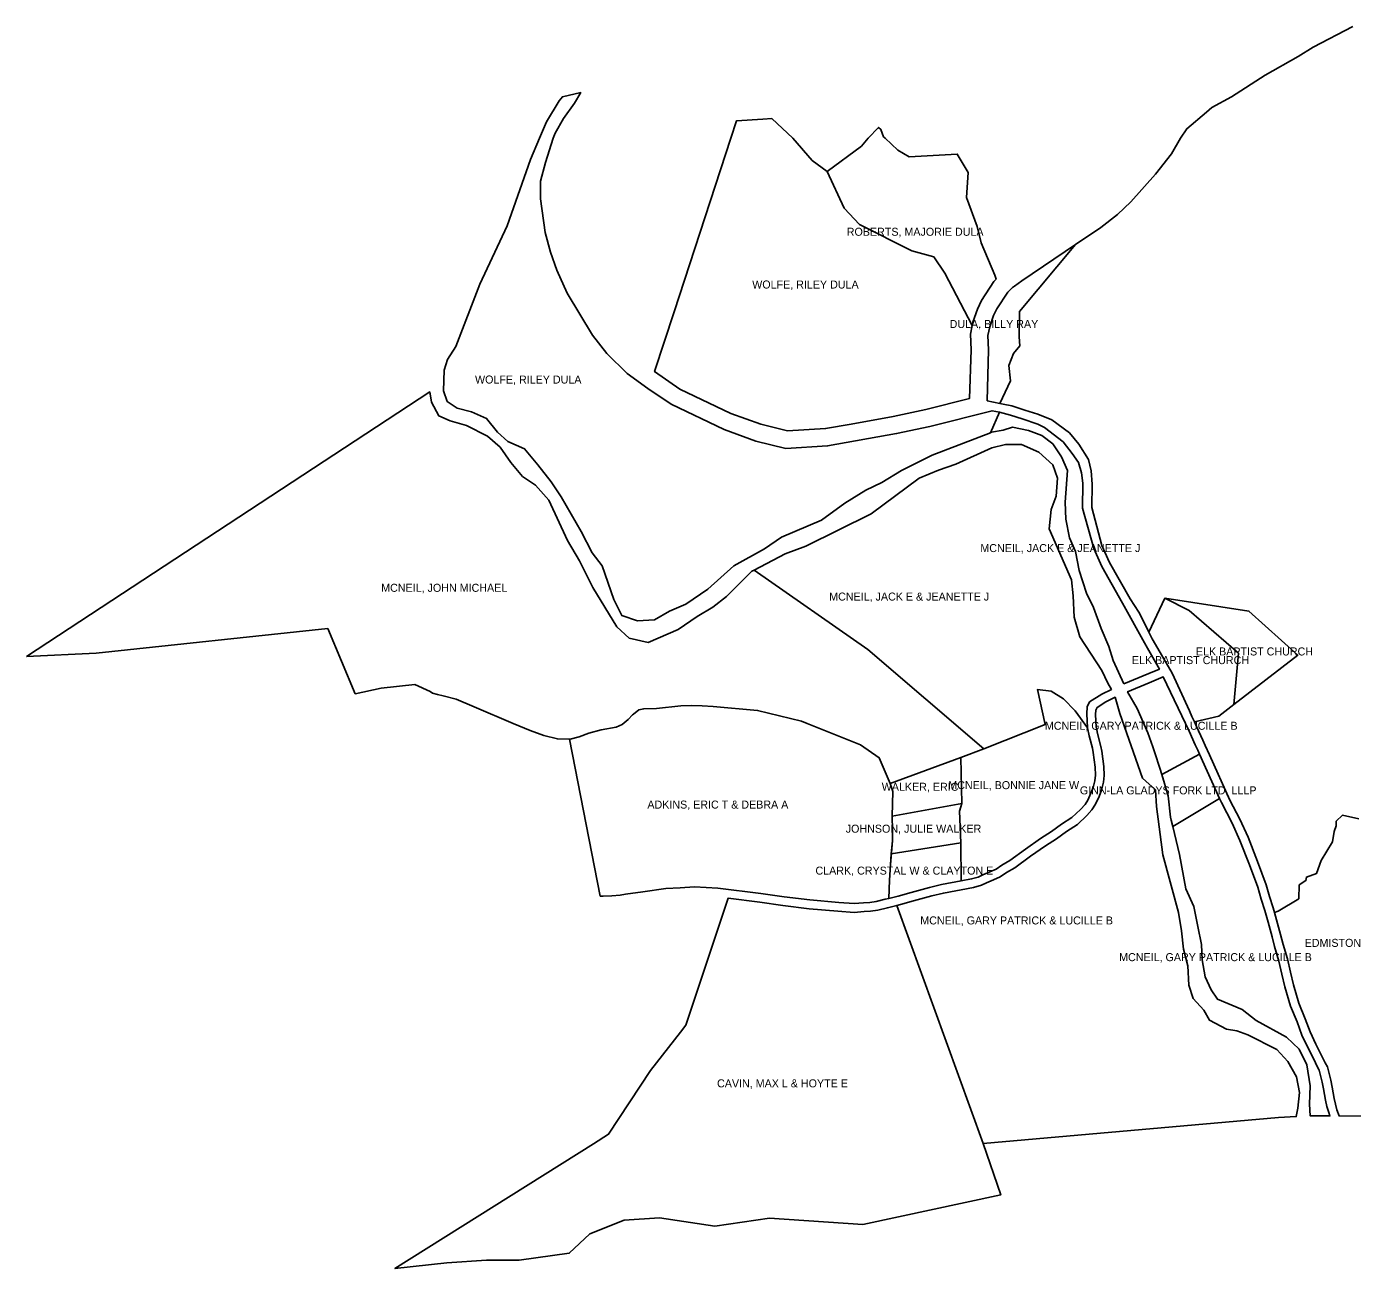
# Model space of a CAD drawing. Extents: x 1282784 to 1290548, y 856119 to 860542.
# Drawn here: x 1282784 to 1287337, y 856119 to 860383 of the extents above; entities that cross this region are included whole.
import ezdxf

# ---------------------------------------------------------------- set-up
doc = ezdxf.new("R2010")
doc.units = 0
doc.layers.add('WILKES_2010PARCELS', color=7, linetype='Continuous')

msp = doc.modelspace()

# ---------------------------------------------------------------- linework, layer by layer
at = {"layer": 'WILKES_2010PARCELS'}
for points in [[(1286746.375, 860000), (1286767.625, 860031.8125), (1286835.375, 860089.0625), (1286853.625, 860104.4375), (1286920.75, 860142.1875), (1287037.125, 860216.1875), (1287149.875, 860279.8125), (1287201.75, 860312.6875), (1287338, 860383)], [(1284545.25, 860000), (1284569.375, 860055.5625), (1284612.25, 860127.5625), (1284623.75, 860141.75), (1284686.375, 860156.5), (1284665.625, 860119.6875), (1284627.75, 860066.6875), (1284598.5, 860016.6875), (1284591.375, 860000)], [(1285201.375, 860000), (1285220.875, 860058.6875), (1285311.25, 860065), (1285342.875, 860067.1875), (1285415.375, 860000)], [(1285673.875, 860000), (1285709.25, 860036.75), (1285717.25, 860030), (1285726, 860004.8125), (1285731.75, 860000)], [(1284591.375, 860000), (1284565, 859916.1875), (1284548.125, 859851.875), (1284548.25, 859791.5), (1284564, 859675.5), (1284582.5, 859608.125), (1284604.125, 859546.3125), (1284639.375, 859467.8125), (1284726.875, 859323.8125), (1284776.375, 859261), (1284845.75, 859191.5625), (1284917, 859140.75), (1284996.875, 859086), (1285178.75, 858999.125), (1285287.625, 858960.0625), (1285391.25, 858934.1875), (1285534.375, 858943), (1285771.125, 858985.4375), (1285884.875, 859010), (1286098.75, 859063.75), (1286125, 859058.8125), (1286093.75, 858988.6875), (1285893, 858911.1875), (1285788.5, 858858.375), (1285720.5, 858818), (1285665.25, 858790.75), (1285592.875, 858747.125), (1285513.625, 858687.9375), (1285376, 858630.3125), (1285317.5, 858589.875), (1285211.875, 858531.0625), (1285123.5, 858451.875), (1285047.875, 858400.25), (1284991.875, 858375.8125), (1284939.75, 858346.1875), (1284881.75, 858342.1875), (1284827.75, 858360.625), (1284799.75, 858415.8125), (1284759.75, 858531.0625), (1284725.75, 858576.6875), (1284687.75, 858649.9375), (1284619.25, 858768.75), (1284585.25, 858820.375), (1284539.625, 858878.8125), (1284493.625, 858933.25), (1284436, 858958.8125), (1284400.875, 858990.8125), (1284363.25, 859037.25), (1284311.125, 859060.0625), (1284262, 859072.875), (1284228, 859096.0625), (1284215.125, 859132.5), (1284218, 859202.9375), (1284229.125, 859239.3125), (1284258, 859284.125), (1284340.375, 859499), (1284433.625, 859698.3125), (1284513.625, 859926.375), (1284545.25, 860000)], [(1285415.375, 860000), (1285480.75, 859923.5625), (1285533.125, 859885.8125), (1285591.25, 859759.125), (1285644, 859703.125), (1285823.375, 859612.6875), (1285898.5, 859592.25), (1285937, 859536.25), (1286030.5, 859356.8125), (1286024.5, 859326.5), (1286026.625, 859273.125), (1286022, 859106.125), (1285871.375, 859068.5), (1285759.375, 859044.3125), (1285615.25, 859018), (1285527.375, 859002.625), (1285396.75, 858994.6875), (1285305.125, 859017.5625), (1285201.75, 859054.625), (1285026.875, 859138.125), (1284939.875, 859198.1875), (1285006.875, 859403.0625), (1285201.375, 860000)], [(1285731.75, 860000), (1285775.125, 859958), (1285813.875, 859936), (1285979.375, 859944.8125), (1286017, 859882.375), (1286011.375, 859796.3125), (1286047.75, 859696.3125), (1286061, 859640.25), (1286108.25, 859529.8125), (1286112.875, 859516.1875), (1286104.5, 859508.1875), (1286062.25, 859442.625), (1286048.875, 859413.125), (1286032.75, 859368.5625), (1286030.5, 859356.8125), (1285937, 859536.25), (1285898.5, 859592.25), (1285823.375, 859612.6875), (1285644, 859703.125), (1285591.25, 859759.125), (1285533.125, 859885.8125), (1285650.5, 859972), (1285673.875, 860000)], [(1287357.875, 857663.375), (1287301.875, 857675.375), (1287281, 857655.375), (1287280.625, 857638.5625), (1287273.375, 857619.75), (1287268.25, 857583.6875), (1287228.625, 857520.4375), (1287213, 857475.5625), (1287178.5, 857463.1875), (1287176.5, 857450.75), (1287153.75, 857436.3125), (1287152.875, 857388.6875), (1287081.25, 857345.8125), (1287068.75, 857341.75), (1287064.375, 857357), (1287051.625, 857396.4375), (1287039.75, 857436.6875), (1287010.5, 857516), (1286978, 857599.75), (1286950, 857661.3125), (1286915.625, 857727.5625), (1286845.125, 857882.6875), (1286830.375, 857915.25), (1286822.125, 857933.1875), (1286800.75, 857979.75), (1286793.5, 857995.625), (1286877.875, 858014.9375), (1286929.625, 858055.0625), (1287149.25, 858225.125), (1286980.75, 858376.0625), (1286692.375, 858420.125), (1286637.375, 858303.625), (1286631.125, 858315.8125), (1286602.5, 858372.1875), (1286573, 858418.5625), (1286502, 858543.375), (1286476, 858601.875), (1286441.375, 858731.9375), (1286442.25, 858811.6875), (1286438.75, 858857.375), (1286430.625, 858896.8125), (1286396.625, 858949.6875), (1286364.375, 858988.25), (1286304.25, 859032.1875), (1286255.875, 859051.875), (1286211.125, 859066.1875), (1286167.375, 859080.875), (1286137.5, 859086.875), (1286125.375, 859089.3125), (1286162.75, 859166.875), (1286156.25, 859219.75), (1286172.25, 859261), (1286193.875, 859287), (1286191.5, 859317.4375), (1286193.5, 859404.75), (1286385.375, 859634.25), (1286472.75, 859693.1875), (1286529.375, 859737.125), (1286575.5, 859780.75), (1286659.75, 859876.6875), (1286715.125, 859946.3125), (1286746.375, 860000)], [(1287423.75, 856642.4375), (1287290.5, 856642.8125), (1287290.25, 856643.75), (1287283.25, 856664.25), (1287277.75, 856683.0625), (1287273.375, 856703), (1287266.5, 856742.0625), (1287261.75, 856765.6875), (1287256, 856788.875), (1287250.875, 856811.8125), (1287243.125, 856824.8125), (1287229.375, 856853.1875), (1287211.125, 856888.875), (1287190.75, 856931.8125), (1287174.625, 856976.5625), (1287151.75, 857030.25), (1287133.625, 857093.625), (1287123.375, 857137.0625), (1287112.875, 857182.4375), (1287098, 857232.0625), (1287089.875, 857265.3125), (1287076, 857316.375), (1287068.75, 857341.75), (1287081.25, 857345.8125), (1287152.875, 857388.6875), (1287153.75, 857436.3125), (1287176.5, 857450.75), (1287178.5, 857463.1875), (1287213, 857475.5625), (1287228.625, 857520.4375), (1287268.25, 857583.6875), (1287273.375, 857619.75), (1287280.625, 857638.5625), (1287281, 857655.375), (1287301.875, 857675.375), (1287357.875, 857663.375)]]:
    msp.add_lwpolyline(points, dxfattribs=at)
for points in [[(1286081.75, 859098), (1286086.625, 859273.5), (1286084.75, 859321.875), (1286090.75, 859352.5625), (1286104.375, 859390.5), (1286115, 859413.75), (1286152.75, 859471.3125), (1286168.75, 859486.75), (1286175.5, 859491.625), (1286201, 859510), (1286385.375, 859634.25), (1286193.5, 859404.75), (1286191.5, 859317.4375), (1286193.875, 859287), (1286172.25, 859261), (1286156.25, 859219.75), (1286162.75, 859166.875), (1286125.375, 859089.3125)], [(1282783.5, 858220.6875), (1284168.25, 859128.3125), (1284173.875, 859092.875), (1284199.125, 859046.0625), (1284238, 859029.625), (1284294.75, 859013.625), (1284366, 858976.4375), (1284409.625, 858938.4375), (1284446, 858886.8125), (1284486.875, 858838), (1284530.875, 858808.75), (1284576.5, 858757.1875), (1284640.875, 858617.9375), (1284681.75, 858549.0625), (1284727.75, 858456.625), (1284811, 858321.8125), (1284853.375, 858283), (1284918.625, 858268.1875), (1285021, 858312.625), (1285085.875, 858357.8125), (1285140.25, 858389.8125), (1285187.5, 858426.625), (1285274.375, 858512.6875), (1285281.75, 858516.5625), (1285672.125, 858244.4375), (1286070.625, 857903.5), (1285992, 857873.875), (1285749.25, 857783.875), (1285711.375, 857872.5625), (1285647.625, 857916.4375), (1285464.25, 857990), (1285444.75, 857997.8125), (1285293.625, 858034.875), (1285141, 858049.0625), (1285103.75, 858050.9375), (1285066.125, 858051.8125), (1285029.875, 858050.6875), (1284947.125, 858041.5), (1284903.125, 858040.625), (1284886, 858036.6875), (1284867.25, 858022.6875), (1284864.625, 858019.875), (1284849.125, 858003.5), (1284829.25, 857986.375), (1284808.5, 857977.125), (1284757, 857968.375), (1284714.25, 857956.8125), (1284681.125, 857944.25), (1284650.25, 857936), (1284648.375, 857936.0625), (1284606.75, 857937.5), (1284559.5, 857949.375), (1284512.5, 857966.375), (1284454.375, 857990.0625), (1284320.5, 858047), (1284258.25, 858073.25), (1284213.625, 858085.4375), (1284194.25, 858089.3125), (1284177.875, 858093.8125), (1284170, 858099.8125), (1284116.875, 858124), (1284001.75, 858111.3125), (1283912.25, 858092.25), (1283818.125, 858316), (1283022.625, 858232.1875)], [(1286551.125, 858126.1875), (1286515.125, 858206.1875), (1286500.375, 858254.1875), (1286473.125, 858316.625), (1286447.125, 858388.25), (1286423.125, 858437.4375), (1286397.875, 858515.5), (1286385.125, 858580.3125), (1286365.125, 858627.125), (1286352.375, 858691.9375), (1286349.875, 858750.375), (1286358.375, 858858.8125), (1286337.125, 858905.1875), (1286307.5, 858950), (1286269.875, 858978.8125), (1286223.5, 858996.4375), (1286169.5, 859007.25), (1286137, 858996.8125), (1286097.375, 858990.0625), (1286093.75, 858988.6875), (1286125, 859058.8125), (1286161.75, 859049.1875), (1286202.125, 859036.625), (1286255.875, 859017.8125), (1286279.125, 859006.1875), (1286342.75, 858957.75), (1286374.125, 858917.4375), (1286395.625, 858886.0625), (1286405.5, 858851.125), (1286410.875, 858815.25), (1286409.125, 858729.25), (1286448, 858590.75), (1286475.5, 858529.125), (1286547, 858403.5625), (1286622.375, 858266.625), (1286632.5, 858248.875), (1286673.625, 858177.1875), (1286637.25, 858162)], [(1286070.625, 857903.5), (1285672.125, 858244.4375), (1285281.75, 858516.5625), (1285388.375, 858572.6875), (1285460, 858599.125), (1285683.25, 858709.9375), (1285848.125, 858832.375), (1285914.5, 858860), (1285974.625, 858880.8125), (1286097.875, 858936.8125), (1286145.5, 858948.4375), (1286199.875, 858947.625), (1286259.125, 858921.625), (1286307.875, 858878.375), (1286323.125, 858832), (1286319.125, 858770.75), (1286301.875, 858724.75), (1286295.5, 858658.3125), (1286371.875, 858483.0625), (1286377.5, 858429.0625), (1286380.375, 858355.4375), (1286400.75, 858287.8125), (1286476.375, 858172.125), (1286496.375, 858128.9375), (1286509, 858107.375), (1286475.375, 858091.25), (1286433.5, 858064.1875), (1286425.875, 858047.125), (1286424, 858023.8125), (1286427, 857975.5625), (1286383.75, 858034.1875), (1286343.75, 858075.375), (1286301.75, 858101.375), (1286255.375, 858107.375), (1286281.5, 857986.75)], [(1286776.375, 858033.25), (1286716.875, 858163.5), (1286651.875, 858275.75), (1286648.875, 858281), (1286637.375, 858303.625), (1286692.375, 858420.125), (1286776.125, 858378.5), (1286945.5, 858231.5625), (1286929.625, 858055.0625), (1286877.875, 858014.9375), (1286793.5, 857995.625), (1286784.875, 858014.5625)], [(1286929.625, 858055.0625), (1286945.5, 858231.5625), (1286776.125, 858378.5), (1286692.375, 858420.125), (1286980.75, 858376.0625), (1287149.25, 858225.125)], [(1285995.5, 857715.4375), (1285992, 857873.875), (1286070.625, 857903.5), (1286281.5, 857986.75), (1286255.375, 858107.375), (1286301.75, 858101.375), (1286343.75, 858075.375), (1286383.75, 858034.1875), (1286427, 857975.5625), (1286432.25, 857948), (1286443.375, 857905.3125), (1286445.875, 857890.875), (1286452.75, 857840.125), (1286454.125, 857812.8125), (1286451.625, 857793.8125), (1286446.375, 857770.5), (1286438.5, 857750.9375), (1286428.125, 857727.25), (1286418.25, 857712.5625), (1286402.5, 857695.5625), (1286373.125, 857667.5625), (1286337.75, 857644.375), (1286303, 857619.3125), (1286265.25, 857595.625), (1286213.25, 857559), (1286160.5, 857520.1875), (1286133, 857503.625), (1286112.75, 857490.1875), (1286091.75, 857481), (1286067.625, 857471.125), (1286051.75, 857463.125), (1286028.625, 857456.6875), (1285992.75, 857449.875), (1285991.75, 857580.4375), (1285987.5, 857689.25)], [(1286650.625, 857910.125), (1286634.375, 857958.0625), (1286596.75, 858042.125), (1286564, 858099), (1286638.875, 858130.1875), (1286686.625, 858150.0625), (1286775.25, 857963.625), (1286796.75, 857916.625), (1286805.125, 857898.1875), (1286811.375, 857884.5), (1286681.625, 857814.875), (1286674.5, 857837.25), (1286657.75, 857889.3125)], [(1286068.625, 856548.25), (1285771.625, 857365.6875), (1285784.5, 857368.9375), (1285829.375, 857381.5625), (1285891.875, 857398.1875), (1285931.75, 857407.8125), (1286035.375, 857427.4375), (1286062.5, 857435), (1286080.125, 857443.75), (1286103.5, 857453.375), (1286127.25, 857463.8125), (1286149, 857478.25), (1286177.25, 857495.1875), (1286230.75, 857534.625), (1286282, 857570.625), (1286319.75, 857594.4375), (1286354.75, 857619.625), (1286391.875, 857643.9375), (1286424, 857674.5625), (1286441.75, 857693.9375), (1286454.375, 857712.75), (1286466.25, 857739.3125), (1286475.125, 857761.625), (1286481.125, 857788.5625), (1286484.125, 857811.5625), (1286482.75, 857842.875), (1286475.625, 857895.5), (1286472.625, 857911.6875), (1286461.25, 857955.625), (1286457.125, 857975.625), (1286456.875, 857977.25), (1286454.25, 858021.1875), (1286455, 858036.1875), (1286460, 858045.5625), (1286490.125, 858065), (1286521.625, 858080.125), (1286537.625, 858024.5), (1286615.25, 857802.8125), (1286660.375, 857762), (1286663.25, 857705.5625), (1286685.25, 857539.125), (1286738.875, 857341.4375), (1286749.625, 857278.625), (1286756, 857215.8125), (1286771.625, 857157.8125), (1286774.5, 857091.75), (1286789.625, 857046.5625), (1286825.625, 857006.125), (1286845.25, 856971.3125), (1286903.75, 856941.3125), (1286939.375, 856935.6875), (1286977.75, 856920.875), (1287076.625, 856870.875), (1287114.625, 856830.0625), (1287143.75, 856777.25), (1287154.25, 856724), (1287149, 856670), (1287143.25, 856641), (1287083, 856637.75)], [(1284752.875, 857397), (1284648.375, 857936.0625), (1284650.25, 857936), (1284681.125, 857944.25), (1284714.25, 857956.8125), (1284757, 857968.375), (1284808.5, 857977.125), (1284829.25, 857986.375), (1284849.125, 858003.5), (1284864.625, 858019.875), (1284867.25, 858022.6875), (1284886, 858036.6875), (1284903.125, 858040.625), (1284947.125, 858041.5), (1285029.875, 858050.6875), (1285066.125, 858051.8125), (1285103.75, 858050.9375), (1285141, 858049.0625), (1285293.625, 858034.875), (1285444.75, 857997.8125), (1285464.25, 857990), (1285647.625, 857916.4375), (1285711.375, 857872.5625), (1285749.25, 857783.875), (1285758.375, 857756.5), (1285756.125, 857672.125), (1285756.25, 857665.125), (1285757.375, 857631.1875), (1285756.625, 857587.625), (1285749.625, 857506.4375), (1285746.25, 857452.1875), (1285744.75, 857389.9375), (1285732.125, 857386.8125), (1285701.125, 857378.625), (1285678.75, 857376), (1285658, 857374.625), (1285625.625, 857371.9375), (1285572.375, 857376), (1285473.625, 857384.375), (1285384.625, 857395.5), (1285305, 857406.6875), (1285157.75, 857424.875), (1285077.5, 857429.125), (1285028.5, 857426.375), (1284978.75, 857423.5), (1284900, 857412.25), (1284839.875, 857403.8125), (1284822, 857401.0625), (1284793.5, 857398.375), (1284763.5, 857397)], [(1286714, 857658.8125), (1286711.625, 857668.75), (1286704, 857742.375), (1286681.625, 857814.875), (1286811.375, 857884.5), (1286879.75, 857733.3125), (1286719.375, 857636.8125)], [(1285756.125, 857672.125), (1285758.375, 857756.5), (1285749.25, 857783.875), (1285992, 857873.875), (1285995.5, 857715.4375)], [(1285752.75, 857542.6875), (1285756.625, 857587.625), (1285757.375, 857631.1875), (1285756.25, 857665.125), (1285756.125, 857672.125), (1285995.5, 857715.4375), (1285987.5, 857689.25), (1285991.75, 857580.4375)], [(1286805.625, 857293), (1286791.625, 857362.25), (1286764.125, 857422.6875), (1286742.875, 857540.75), (1286719.375, 857636.8125), (1286879.75, 857733.3125), (1286886.25, 857719), (1286923, 857648.1875), (1286950.25, 857588.125), (1286982.5, 857505.375), (1287011, 857427.8125), (1287023.125, 857387.3125), (1287035.625, 857348.25), (1287047, 857308.25), (1287060.875, 857257.8125), (1287069, 857224.1875), (1287083.875, 857174.6875), (1287094.125, 857130.1875), (1287104.625, 857086), (1287123.5, 857020.25), (1287146.625, 856965.5625), (1287163, 856920.3125), (1287184.125, 856875.625), (1287202.625, 856839.8125), (1287216.625, 856810.5625), (1287222.625, 856800.5625), (1287226.75, 856782), (1287232.5, 856759.0625), (1287237, 856736.5625), (1287243.875, 856697.125), (1287248.75, 856675.5625), (1287254.75, 856655.25), (1287258.875, 856642.9375), (1287191.625, 856643.1875), (1287188.625, 856683.1875), (1287191.375, 856746.8125), (1287179.875, 856818.0625), (1287153.375, 856871.6875), (1287110.25, 856913.6875), (1287006.125, 856970.5), (1286958.125, 857008.125), (1286872.875, 857043.3125), (1286851.75, 857075.75), (1286830.875, 857120.1875), (1286820.125, 857178.5625), (1286818.125, 857231.8125)], [(1285749.625, 857506.4375), (1285752.75, 857542.6875), (1285991.75, 857580.4375), (1285992.75, 857449.875), (1285925.5, 857437.1875), (1285884.375, 857427.3125), (1285821.375, 857410.4375), (1285776.75, 857397.9375), (1285744.75, 857389.9375), (1285746.25, 857452.1875)], [(1284729.875, 856547), (1284782.375, 856580), (1284926.375, 856798.875), (1285028.875, 856930.8125), (1285047.25, 856954.5625), (1285192.375, 857390.375), (1285301, 857376.9375), (1285380.625, 857365.75), (1285470.375, 857354.5), (1285569.875, 857346.125), (1285625.625, 857341.8125), (1285660.25, 857344.75), (1285681.5, 857346.125), (1285706.625, 857349.125), (1285739.625, 857357.6875), (1285771.625, 857365.6875), (1286068.625, 856548.25), (1286129, 856372), (1285655.625, 856270.6875), (1285335.125, 856291.5), (1285147.125, 856265.0625), (1284957.375, 856293.0625), (1284836.125, 856284.6875), (1284718.125, 856238.625), (1284647.25, 856171.8125), (1284475.25, 856147.4375), (1284363.25, 856147.4375), (1284226.75, 856139), (1284048.75, 856119.3125)]]:
    msp.add_lwpolyline(points, close=True, dxfattribs=at)

# ---------------------------------------------------------------- texts
for s, p in [('ROBERTS, MAJORIE DULA', (1285599.984931, 859664.665754)), ('WOLFE, RILEY DULA', (1285275.295794, 859483.603254)), ('DULA, BILLY RAY', (1285953.211439, 859348.040754)), ('WOLFE, RILEY DULA', (1284323.437893, 859157.353254)), ('MCNEIL, JACK E & JEANETTE J', (1286058.750615, 858578.759504)), ('MCNEIL, JOHN MICHAEL', (1284001.376245, 858442.353254)), ('MCNEIL, JACK E & JEANETTE J', (1285539.702904, 858412.228254)), ('ELK BAPTIST CHURCH', (1286798.770506, 858223.853254)), ('ELK BAPTIST CHURCH', (1286579.105641, 858194.134504)), ('MCNEIL, GARY PATRICK & LUCILLE B', (1286280.366832, 857968.728254)), ('MCNEIL, BONNIE JANE W', (1285948.634613, 857764.884504)), ('WALKER, ERIC', (1285720.116163, 857759.259504)), ('GINN-LA GLADYS FORK LTD, LLLP', (1286400.427062, 857746.915754)), ('ADKINS, ERIC T & DEBRA A', (1284915.348782, 857698.134504)), ('JOHNSON, JULIE WALKER', (1285596.494607, 857615.322004)), ('CLARK, CRYSTAL W & CLAYTON E', (1285492.527626, 857471.447004)), ('MCNEIL, GARY PATRICK & LUCILLE B', (1285852.432639, 857300.447004)), ('EDMISTON, GEORGE S & CHARLOTTE M', (1287172.215952, 857223.415754)), ('MCNEIL, GARY PATRICK & LUCILLE B', (1286535.296442, 857174.384504)), ('CAVIN, MAX L & HOYTE E', (1285154.644298, 856741.103254))]:
    msp.add_text(s, height=27.480992, dxfattribs=at).set_placement(p)

doc.saveas('drawing.dxf')
